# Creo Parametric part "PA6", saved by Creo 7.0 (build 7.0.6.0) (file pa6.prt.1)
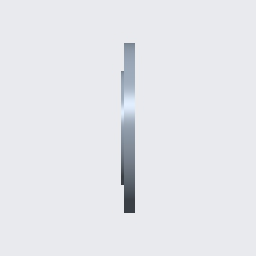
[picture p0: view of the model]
Units: Inch lbm Second (Pro/E Default); INCH, POUND, SECS

Created from: XX_INLBS_PART_SOLID_ABS.PRT

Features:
  1. datum plane "RIGHT"
  2. datum plane "TOP"
  3. datum plane "FRONT"
  4. coordinate system
  5. revolve "Revolve 1"
  6. pattern "Pattern 1"
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
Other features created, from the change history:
  hole "Hole 1" (2 times)
  pattern "Pattern 1"
  hole "Hole 1 [2]" (2 times)
  hole "Hole 1 [3]" (2 times)
  hole "Hole 1 [4]" (2 times)
  hole "Hole 2"
  pattern "Pattern 2"
  hole "Hole 2 [2]"
  hole "Hole 2 [3]"
  hole "Hole 2 [4]"
  hole "Hole 2 [5]"
  hole "Hole 2 [6]"
  chamfer "Chamfer 1"
  planar section "XSEC0001"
